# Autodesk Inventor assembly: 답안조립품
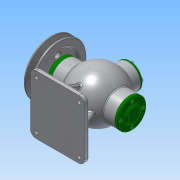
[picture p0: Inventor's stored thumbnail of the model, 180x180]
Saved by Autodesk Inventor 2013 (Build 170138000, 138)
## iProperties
Created: 2018-06
Part Number: 답안조립품
Document SubType Name: Assembly
Designer: Administrator
Author: Administrator
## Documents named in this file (19)
- C:\Users\Administrator\Desktop\480612V1019\답안조립품.iam
- C:\Users\Administrator\Desktop\480612V1019\본체.ipt
- C:\Users\Administrator\Desktop\480612V1019\V-벨트풀리.ipt
- C:\Users\Administrator\Desktop\480612V1019\너트 M8.ipt
- C:\Users\Administrator\Desktop\480612V1019\뒤커버.ipt
- C:\Users\Administrator\Desktop\480612V1019\멈춤링 15x1.ipt
- C:\Users\Administrator\Desktop\480612V1019\멈춤링 35x1.6.ipt
- 멈춤링 35x1.6.ipt
- C:\Users\Administrator\Desktop\480612V1019\베어링 6202.ipt
- 베어링 6202.ipt
- C:\Users\Administrator\Desktop\480612V1019\볼트 M4x12.ipt
- C:\Users\Administrator\Desktop\480612V1019\볼트 M4x16.ipt
- C:\Users\Administrator\Desktop\480612V1019\부시.ipt
- C:\Users\Administrator\Desktop\480612V1019\상부커버.ipt
- C:\Users\Administrator\Desktop\480612V1019\슬라이드.ipt
- C:\Users\Administrator\Desktop\480612V1019\앞커버.ipt
- C:\Users\Administrator\Desktop\480612V1019\오일 실 15 30 7.ipt
- C:\Users\Administrator\Desktop\480612V1019\키 4x4x12.ipt
- C:\Users\Administrator\Desktop\480612V1019\편심축.ipt
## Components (1 placed, 1 different names)
1. V-벨트풀리:1
